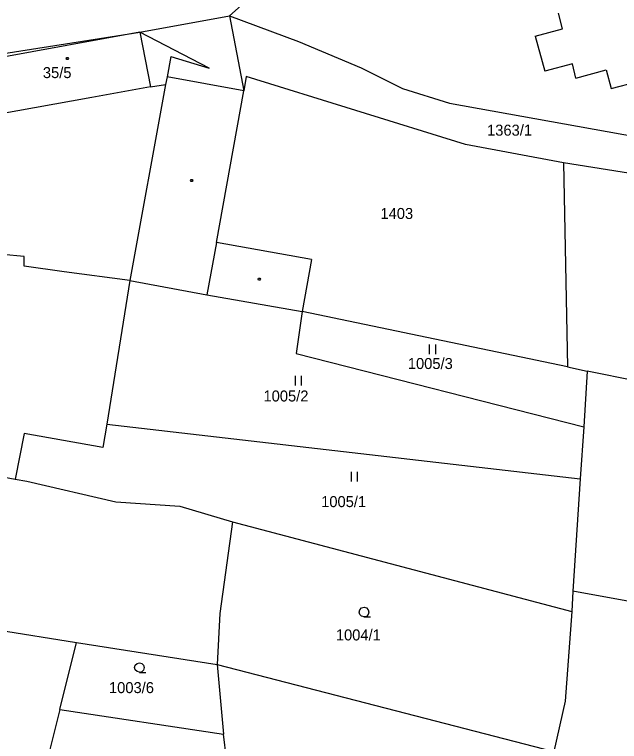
# Model space of a CAD drawing. Extents: x -852001 to -842497, y -1063614 to -1052182.
# Drawn here: x -844356.3 to -844262.9, y -1061526.1 to -1061413.7 of the extents above; entities that cross this region are included whole.
import ezdxf

# ---------------------------------------------------------------- set-up
doc = ezdxf.new("R2010")
doc.units = 0
for name, color, linetype in [('Default', 7, 'Continuous'), ('KN_HRANICE', 7, 'Continuous'), ('KN_KULTURY', 7, 'Continuous'), ('KN_PARCELY', 7, 'Continuous'), ('KN_SLUCKY', 7, 'Continuous')]:
    doc.layers.add(name, color=color, linetype=linetype)

# ---------------------------------------------------------------- blocks, each defined once
blk = doc.blocks.new('304')
at = {"layer": 'Default'}
blk.add_lwpolyline([(0, 0), (-0.38, 0.1), (-0.65, 0.37), (-0.75, 0.74), (-0.65, 1.11), (-0.38, 1.38), (-0.01, 1.48), (0.36, 1.38), (0.63, 1.11), (0.73, 0.73), (0.63, 0.35), (0.36, 0.08), (-0.02, -0.02), (0.98, -0.02)], dxfattribs=at)
blk = doc.blocks.new('306')
at = {"layer": 'Default'}
for p, q in [((-0.5, 1.5), (-0.5, 0)), ((0.5, 0), (0.5, 1.5))]:
    blk.add_line(p, q, dxfattribs=at)
blk = doc.blocks.new('402')
at = {"layer": 'Default'}
blk.add_lwpolyline([(0.09, 0.15), (0.18, 0), (0.09, -0.15), (-0.09, -0.15), (-0.18, 0), (-0.09, 0.15), (0.09, 0.15)], dxfattribs=at)

msp = doc.modelspace()

# ---------------------------------------------------------------- linework, layer by layer
at = {"layer": 'KN_HRANICE'}
for p, q in [((-844311.38, -1061403.28), (-844323.12, -1061413.92)), ((-844311.38, -1061403.28), (-844323.12, -1061413.92)), ((-844337.01, -1061416.42), (-844323.12, -1061413.92)), ((-844337.01, -1061416.42), (-844323.12, -1061413.92)), ((-844323.12, -1061413.92), (-844320.91, -1061425.5)), ((-844323.12, -1061413.92), (-844312.48, -1061417.88)), ((-844323.12, -1061413.92), (-844320.91, -1061425.5)), ((-844323.12, -1061413.92), (-844312.48, -1061417.88)), ((-844271.7, -1061415.94), (-844272.32, -1061413.52)), ((-844271.7, -1061415.94), (-844272.32, -1061413.52)), ((-844374.69, -1061422.36), (-844337.01, -1061416.42)), ((-844374.69, -1061422.36), (-844337.01, -1061416.42)), ((-844337.01, -1061416.42), (-844360.59, -1061420.77)), ((-844337.01, -1061416.42), (-844360.59, -1061420.77)), ((-844275.92, -1061417.08), (-844271.7, -1061415.94)), ((-844275.92, -1061417.08), (-844271.7, -1061415.94)), ((-844312.48, -1061417.88), (-844302.78, -1061421.94)), ((-844312.48, -1061417.88), (-844302.78, -1061421.94)), ((-844275.92, -1061417.08), (-844274.43, -1061422.48)), ((-844275.92, -1061417.08), (-844274.43, -1061422.48)), ((-844302.78, -1061421.94), (-844296.41, -1061425.13)), ((-844302.78, -1061421.94), (-844296.41, -1061425.13)), ((-844270.17, -1061421.34), (-844274.43, -1061422.48)), ((-844270.17, -1061421.34), (-844274.43, -1061422.48)), ((-844269.61, -1061423.58), (-844270.17, -1061421.34)), ((-844269.61, -1061423.58), (-844270.17, -1061421.34)), ((-844269.61, -1061423.58), (-844264.95, -1061422.29)), ((-844269.61, -1061423.58), (-844264.95, -1061422.29)), ((-844264.95, -1061422.29), (-844264.16, -1061425.17)), ((-844264.95, -1061422.29), (-844264.16, -1061425.17)), ((-844320.54, -1061423.3), (-844320.91, -1061425.5)), ((-844320.54, -1061423.3), (-844320.91, -1061425.5)), ((-844286.69, -1061433.79), (-844320.54, -1061423.3)), ((-844286.69, -1061433.79), (-844320.54, -1061423.3)), ((-844264.16, -1061425.17), (-844255.09, -1061422.7)), ((-844264.16, -1061425.17), (-844255.09, -1061422.7)), ((-844325.16, -1061448.99), (-844320.91, -1061425.5)), ((-844325.16, -1061448.99), (-844320.91, -1061425.5)), ((-844296.41, -1061425.13), (-844289.17, -1061427.44)), ((-844296.41, -1061425.13), (-844289.17, -1061427.44)), ((-844289.17, -1061427.44), (-844237.33, -1061436.72)), ((-844289.17, -1061427.44), (-844237.33, -1061436.72)), ((-844271.55, -1061436.64), (-844286.69, -1061433.79)), ((-844271.55, -1061436.64), (-844286.69, -1061433.79)), ((-844213.45, -1061446), (-844271.55, -1061436.64)), ((-844271.55, -1061436.64), (-844270.91, -1061468.18)), ((-844213.45, -1061446), (-844271.55, -1061436.64)), ((-844271.55, -1061436.64), (-844270.91, -1061468.18)), ((-844310.49, -1061451.61), (-844325.16, -1061448.99)), ((-844310.49, -1061451.61), (-844325.16, -1061448.99)), ((-844354.84, -1061451.14), (-844358.19, -1061450.8)), ((-844354.84, -1061451.14), (-844358.19, -1061450.8)), ((-844354.84, -1061452.65), (-844354.84, -1061451.14)), ((-844354.84, -1061452.65), (-844354.84, -1061451.14)), ((-844310.49, -1061451.61), (-844311.93, -1061459.63)), ((-844310.49, -1061451.61), (-844311.93, -1061459.63)), ((-844348.7, -1061453.49), (-844354.84, -1061452.65)), ((-844348.7, -1061453.49), (-844354.84, -1061452.65)), ((-844338.51, -1061454.86), (-844348.7, -1061453.49)), ((-844338.51, -1061454.86), (-844348.7, -1061453.49)), ((-844338.51, -1061454.86), (-844342.11, -1061477.05)), ((-844338.51, -1061454.86), (-844342.11, -1061477.05)), ((-844338.51, -1061454.86), (-844326.62, -1061457.05)), ((-844338.51, -1061454.86), (-844326.62, -1061457.05)), ((-844326.62, -1061457.05), (-844311.93, -1061459.63)), ((-844326.62, -1061457.05), (-844311.93, -1061459.63)), ((-844311.93, -1061459.63), (-844312.83, -1061466.13)), ((-844311.93, -1061459.63), (-844312.83, -1061466.13)), ((-844270.91, -1061468.18), (-844311.93, -1061459.63)), ((-844270.91, -1061468.18), (-844311.93, -1061459.63)), ((-844312.83, -1061466.13), (-844268.42, -1061477.46)), ((-844312.83, -1061466.13), (-844268.42, -1061477.46)), ((-844270.91, -1061468.18), (-844267.86, -1061468.88)), ((-844270.91, -1061468.18), (-844267.86, -1061468.88)), ((-844267.86, -1061468.88), (-844268.42, -1061477.46)), ((-844267.86, -1061468.88), (-844268.42, -1061477.46)), ((-844183.22, -1061486.06), (-844267.86, -1061468.88)), ((-844183.22, -1061486.06), (-844267.86, -1061468.88)), ((-844342.11, -1061477.05), (-844342.69, -1061480.64)), ((-844342.11, -1061477.05), (-844342.69, -1061480.64)), ((-844342.11, -1061477.05), (-844268.94, -1061485.5)), ((-844342.11, -1061477.05), (-844268.94, -1061485.5)), ((-844268.42, -1061477.46), (-844268.94, -1061485.5)), ((-844268.42, -1061477.46), (-844268.94, -1061485.5)), ((-844354.87, -1061478.49), (-844356.25, -1061485.54)), ((-844354.87, -1061478.49), (-844356.25, -1061485.54)), ((-844342.69, -1061480.64), (-844354.87, -1061478.49)), ((-844342.69, -1061480.64), (-844354.87, -1061478.49)), ((-844360.41, -1061484.77), (-844356.25, -1061485.54)), ((-844360.41, -1061484.77), (-844356.25, -1061485.54)), ((-844356.25, -1061485.54), (-844354.47, -1061485.87)), ((-844356.25, -1061485.54), (-844354.47, -1061485.87)), ((-844354.47, -1061485.87), (-844340.71, -1061489.06)), ((-844354.47, -1061485.87), (-844340.71, -1061489.06)), ((-844268.94, -1061485.5), (-844270.08, -1061502.89)), ((-844268.94, -1061485.5), (-844270.08, -1061502.89)), ((-844340.71, -1061489.06), (-844330.81, -1061489.72)), ((-844340.71, -1061489.06), (-844330.81, -1061489.72)), ((-844330.81, -1061489.72), (-844322.67, -1061492.14)), ((-844330.81, -1061489.72), (-844322.67, -1061492.14)), ((-844322.67, -1061492.14), (-844324.65, -1061506.34)), ((-844322.67, -1061492.14), (-844324.65, -1061506.34)), ((-844322.67, -1061492.14), (-844270.27, -1061506.03)), ((-844322.67, -1061492.14), (-844270.27, -1061506.03)), ((-844270.08, -1061502.89), (-844270.27, -1061506.03)), ((-844270.08, -1061502.89), (-844270.27, -1061506.03)), ((-844183.75, -1061518.46), (-844270.08, -1061502.89)), ((-844183.75, -1061518.46), (-844270.08, -1061502.89)), ((-844324.65, -1061506.34), (-844325.04, -1061514.23)), ((-844324.65, -1061506.34), (-844325.04, -1061514.23)), ((-844270.27, -1061506.03), (-844271.27, -1061519.86)), ((-844270.27, -1061506.03), (-844271.27, -1061519.86)), ((-844364.61, -1061507.99), (-844346.8, -1061510.8)), ((-844364.61, -1061507.99), (-844346.8, -1061510.8)), ((-844349.36, -1061521.16), (-844346.8, -1061510.8)), ((-844349.36, -1061521.16), (-844346.8, -1061510.8)), ((-844346.8, -1061510.8), (-844325.04, -1061514.23)), ((-844346.8, -1061510.8), (-844325.04, -1061514.23)), ((-844325.04, -1061514.23), (-844324.04, -1061525.01)), ((-844325.04, -1061514.23), (-844273.04, -1061527.65)), ((-844325.04, -1061514.23), (-844324.04, -1061525.01)), ((-844325.04, -1061514.23), (-844273.04, -1061527.65)), ((-844271.27, -1061519.86), (-844273.04, -1061527.65)), ((-844271.27, -1061519.86), (-844273.04, -1061527.65)), ((-844349.36, -1061521.16), (-844353.34, -1061537.33)), ((-844349.36, -1061521.16), (-844353.34, -1061537.33)), ((-844349.36, -1061521.16), (-844324.04, -1061525.01)), ((-844349.36, -1061521.16), (-844324.04, -1061525.01)), ((-844321.96, -1061541.94), (-844324.04, -1061525.01)), ((-844321.96, -1061541.94), (-844324.04, -1061525.01))]:
    msp.add_line(p, q, dxfattribs=at)
at = {"layer": 'KN_SLUCKY'}
for p, q in [((-844326.27, -1061421.99), (-844337.01, -1061416.42)), ((-844337.01, -1061416.42), (-844335.33, -1061424.9)), ((-844326.27, -1061421.99), (-844337.01, -1061416.42)), ((-844337.01, -1061416.42), (-844335.33, -1061424.9)), ((-844332.2, -1061420.23), (-844332.77, -1061423.35)), ((-844332.2, -1061420.23), (-844332.77, -1061423.35)), ((-844332.2, -1061420.23), (-844326.27, -1061421.99)), ((-844332.2, -1061420.23), (-844326.27, -1061421.99)), ((-844332.77, -1061423.35), (-844333.04, -1061424.56)), ((-844332.77, -1061423.35), (-844333.04, -1061424.56)), ((-844320.91, -1061425.5), (-844332.77, -1061423.35)), ((-844320.91, -1061425.5), (-844332.77, -1061423.35)), ((-844333.04, -1061424.56), (-844338.51, -1061454.86)), ((-844333.04, -1061424.56), (-844338.51, -1061454.86)), ((-844335.33, -1061424.9), (-844333.04, -1061424.56)), ((-844335.33, -1061424.9), (-844333.04, -1061424.56)), ((-844335.33, -1061424.9), (-844344.39, -1061426.55)), ((-844335.33, -1061424.9), (-844344.39, -1061426.55)), ((-844344.39, -1061426.55), (-844359.06, -1061429.16)), ((-844344.39, -1061426.55), (-844359.06, -1061429.16)), ((-844325.16, -1061448.99), (-844326.62, -1061457.05)), ((-844325.16, -1061448.99), (-844326.62, -1061457.05))]:
    msp.add_line(p, q, dxfattribs=at)

# ---------------------------------------------------------------- block references
at = {"layer": 'KN_KULTURY'}
for name, p in [('402', (-844348.18, -1061420.51)), ('402', (-844348.18, -1061420.51)), ('402', (-844328.97, -1061439.38)), ('402', (-844328.97, -1061439.38)), ('402', (-844318.55, -1061454.62)), ('402', (-844318.55, -1061454.62)), ('306', (-844291.78, -1061466.24)), ('306', (-844291.78, -1061466.24)), ('306', (-844312.5, -1061471.07)), ('306', (-844312.5, -1061471.07)), ('306', (-844303.86, -1061485.94)), ('306', (-844303.86, -1061485.94)), ('304', (-844302.34, -1061506.85)), ('304', (-844302.34, -1061506.85)), ('304', (-844337.04, -1061515.42)), ('304', (-844337.04, -1061515.42))]:
    msp.add_blockref(name, p, dxfattribs=at)

# ---------------------------------------------------------------- texts
at = {"layer": 'KN_PARCELY'}
for s, p in [('35/5', (-844351.97, -1061423.55)), ('35/5', (-844351.97, -1061423.55)), ('1363/1', (-844283.35, -1061432.45)), ('1363/1', (-844283.35, -1061432.45)), ('1403', (-844299.82, -1061445.33)), ('1403', (-844299.82, -1061445.33)), ('1005/3', (-844295.59, -1061468.53)), ('1005/3', (-844295.59, -1061468.53)), ('1005/2', (-844317.89, -1061473.55)), ('1005/2', (-844317.89, -1061473.55)), ('1005/1', (-844308.98, -1061489.88)), ('1005/1', (-844308.98, -1061489.88)), ('1004/1', (-844306.71, -1061510.49)), ('1004/1', (-844306.71, -1061510.49)), ('1003/6', (-844341.76, -1061518.64)), ('1003/6', (-844341.76, -1061518.64))]:
    msp.add_text(s, height=1.7, dxfattribs=at).set_placement(p)

doc.saveas('drawing.dxf')
